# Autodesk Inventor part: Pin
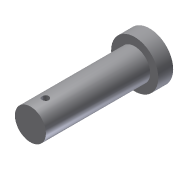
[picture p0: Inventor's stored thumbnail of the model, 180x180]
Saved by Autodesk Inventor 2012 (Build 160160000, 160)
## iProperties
Created: 2011-09
Part Number: Pin
Material: Default
Document SubType Name: Modeling
Designer: CADCIM
Density: 1 g/cm^3
Author: CADCIM
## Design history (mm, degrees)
sketch "Sketch1"
  geometry: 1 further point
sketch "Sketch2"
  geometry: C1 r 12.5 at (0, 0); 1 further point
  constraints: 1 centre point, 1 coincident
  dimensions: "d0" = 25 diameter of C1
extrude "Extrusion1" new body sketch "Sketch2" stored distance "d1" = 84; taper "d2" = 0 deg
sketch "Sketch3"
  geometry: C1 r 12.5 at (0, 0) reference; C2 r 19 at (0, 0)
  constraints: 1 centre point, 1 coincident
  dimensions: "d4" = 38 diameter of C2
extrude "Extrusion2" join sketch "Sketch3" distance "d5" = 12; taper "d6" = 0 deg
sketch "Sketch4"
  geometry: L1 (0, 0)-(0, -60); L2 (12.5, -42)-(-12.5, -42) reference; C1 r 2.75 at (0, -30)
  constraints: 2 end point, 1 centre point, 1 midpoint, 1 vertical
  dimensions: "d7" = 5.5 diameter of C1; "d8" = 12 distance from line of C1.centre L2
extrude "Extrusion3" cut sketch "Sketch4" stored distance "d9" = 12; taper "d10" = 0 deg
body "Solid1"
